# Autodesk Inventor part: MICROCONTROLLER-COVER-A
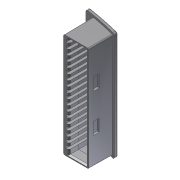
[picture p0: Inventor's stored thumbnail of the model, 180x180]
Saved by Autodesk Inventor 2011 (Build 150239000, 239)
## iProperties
Created: 2010-06
Part Number: MICROCONTROLLER-COVER-A
Document SubType Name: Modeling
Designer: kurdi
Density: 1 g/cm^3
Author: kurdi
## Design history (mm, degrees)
feature "Base1"
node "NONE"
